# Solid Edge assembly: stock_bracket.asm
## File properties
Author: Deepak Maini
Template: Normal.asm
Last saved by: CADCIM Technologies
Revision: 25
Application: Solid Edge
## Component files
adjusting_screw_guide.par
adjusting_nut_handle.par
stock_support_roller.par
Stock_support_base.par
thrust_bearing.par
adjusting_screw_nut.par
support_adjusting_screw.par
support_roller_bracket.par
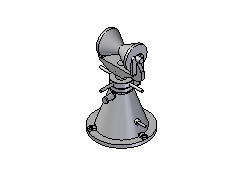
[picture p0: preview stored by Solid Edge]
